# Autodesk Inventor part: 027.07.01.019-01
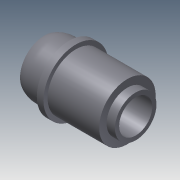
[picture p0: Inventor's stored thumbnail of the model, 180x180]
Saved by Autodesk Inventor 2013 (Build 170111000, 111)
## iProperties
Shininess: 25.0
Length Units: 11269
Angle Units: 11279
Time Units: 11290
Mass Units: 11283
Length Display Precision: 3
Angle Display Precision: 2
Created: 2001-11
Part Number: 027.07.01.019-01
Document SubType Name: Modeling
Designer: SOleg
Material: Steel, Mild
Density: 7.86 g/cm^3
Density: 0.0
Volumn: 0.0
Area: 0.0
PropertySet Name: Model Information
Control State: 0
Master: False
Checked Out: True
Checked Out Date: 2008-10-15
Last Check In Date: 2008-10-15
Author: SOleg
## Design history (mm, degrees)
body "Solid1"
revolve "RevolutionAngle1" stored, may be unused: angle "d24" = 360 deg
sketch "Sketch1"
  geometry: L1 (-25.5, 16.5)-(-19.232, 16.5); L2 (-32.5, 14.624)-(-32.5, 10); L3 (-32.5, 10)-(22.5, 10); L4 (22.5, 12.5)-(22.5, 10); L5 (22.5, 12.5)-(17.5, 12.5); L6 (17.5, 12.5)-(17.5, 17); L7 (17.5, 17)-(-13.5, 17); L8 (-13.5, 17)-(-13.5, 19.5); L9 (-13.5, 19.5)-(-17.5, 19.5); L10 (-19.232, 16.5)-(-17.5, 19.5); L11 (-27.5, 0)-(27.5, 0); L12 (-27.5, 0)-(27.5, 0); A1 r 14 centre (-25.5, 2.5) between (-25.5, 16.5) and (-32.5, 14.624)
  constraints: 24 end point, 6 horizontal, 4 vertical, 2 point on circle, 1 centre point, 1 other
  dimensions: "d1" = 55 distance of L2.end L3.end; "d3" = 19.5 vertical distance of L9.end L11.start; "d5" = 17 vertical distance of L6.end L11.end; "d7" = 12.5 vertical distance of L4.start L11.end; "d9" = 10 vertical distance of L3.end L11.end; "d11" = 120 deg angle of L10 L9; "d13" = 7 horizontal distance of L2.end A1.centre; "d15" = 4 distance of L8.end L9.end; "d17" = 19 horizontal distance of L7.end L2.end; "d19" = 14 radius of A1; "d21" = 16.5 vertical distance of L1.start L11.start; "d23" = 5 distance of L4.start L5.end
other parameters: "d0" = 55 (derived), "d2" = 19.5 (derived), "d4" = 17 (derived), "d6" = 15.5 (derived), "d10" = 120 deg (derived), "d12" = 7 (derived), "d14" = 4 (derived), "d16" = 19 (derived), "d18" = 14 (derived), "d20" = 16.5 (derived), "d22" = 5 (derived)
